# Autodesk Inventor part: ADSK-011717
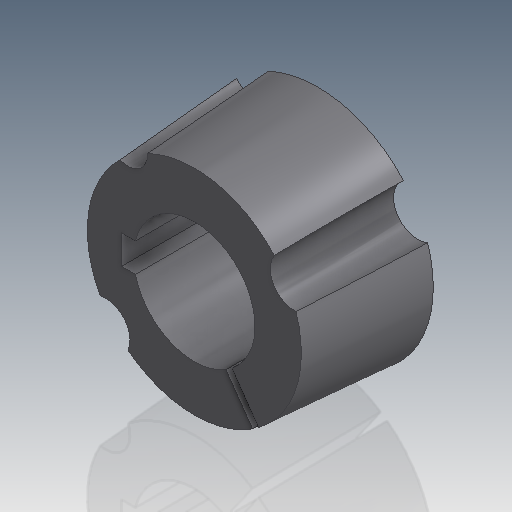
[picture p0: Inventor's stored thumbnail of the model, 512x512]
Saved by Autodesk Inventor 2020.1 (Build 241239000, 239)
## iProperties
Created: 1999-11
Part Number: ADSK-011717
Material: Acier doux
Description: BUSH,TL,1.00B,1.875
Document SubType Name: Modeling
Designer: dmcquary
Density: 7.86 g/cm^3
Appearance: Metal-Steel(Polish)
Mass: 210.363 g
Surface Area: 85.9295 cm^2
Volume: 26.7637 cm^3
Control State: 0
Checked Out: False
Last Check In By: sspink
Last Check In Date: 1999-12-22
Master: False
Shininess: 0.0
Length Units: 11269
Angle Units: 11279
Time Units: 11290
Mass Units: 11283
Length Display Precision: 3
Angle Display Precision: 2
Compacted: True
Dimensions: 47,6x47,6x25,4 mm
Mass: 0,21 kg
DocNumber: ADSK-011717.ipt
Folder: 01 - Themengebiete\Simplification\01 - Packaging machine\
VDS_Category: 3D Komponenten
Density: 0.0
Volumn: 0.0
Area: 0.0
PropertySet Name: Model Information
Author: dmcquary
Revision Number: -
Title: BUSH,TL,1.00B,1.875
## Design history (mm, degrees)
node "Solide1"
  node "Extrusion1" dims "d1" = 25.4, "d2" = -4 deg
  node "Extrusion2" dims "d8" = 25.4, "d9" = 0
  node "Hole1" dims "d15" = 10, "d16" = 9.525, "d17" = 6.35, "d18" = 60 deg, "d19" = 25.4, "d20" = 118 deg, "d36" = 6
  node "Hole2" dims "d23" = 8, "d24" = 9.525, "d25" = 6.35, "d26" = 60 deg, "d27" = 22.2, "d28" = 118 deg, "d37" = 16
  node "Extrusion3" dims "d32" = 25.4, "d33" = 0
sketch "Sketch2"
  geometry: L1 (0, 0)-(18.01, 0); L2 (9, 3)-(15, 3); L3 (15, 3)-(15, -3); L4 (15, -3)-(9, -3); L5 (9, -3)-(9, 3); C1 r 23.812 at (0, 0) reference; C2 r 12.5 at (0, 0)
  constraints: 10 end point, 2 coincident, 2 horizontal, 2 parallel, 2 perpendicular, 1 centre point
  dimensions: "d3" = 25 diameter of C2; "d4" = 6 distance of L3.end L4.end; "d6" = 3 distance from line of C1.centre L2; "d7" = 15 distance from line of L3 C2.centre
sketch "Sketch3"
  geometry: L1 (-15, 3)-(-12.135, 3) reference; L2 (0, 0)-(-23.812, 0); L3 (0, 0)-(-18.241, -15.306); L4 (0, 0)-(20.622, 11.906); C1 r 22.036 at (0, 0) reference; A1 r 23.812 centre (0, 0) between (-23.812, 0) and (-18.241, -15.306); 2 further points
  constraints: 6 end point, 3 coincident, 3 point on circle, 1 centre point, 1 parallel
  dimensions: "d10" = 47.625 diameter of A1; "d12" = 40 deg angle of L3 L2; "d14" = 170 deg angle of L4 L3
workaxis "Work Axis1"
sketch "Sketch6"
  geometry: L1 (-6.558, -7.982)-(-5.258, -8.893); L2 (-5.258, -8.893)-(-17.181, -25.921); L3 (-17.181, -25.921)-(-18.481, -25.01); L4 (-18.481, -25.01)-(-6.558, -7.982); L5 (13.658, 19.506)-(0, 0); A1 r 12.5 centre (0, 0) between (12.135, 3) and (12.135, -3) reference; A2 r 4 centre (13.658, 19.506) between (10.201, 21.517) and (16.731, 16.945) reference; A3 r 23.812 centre (0, 0) between (21.035, -11.16) and (16.731, 16.945) reference
  constraints: 10 end point, 3 parallel, 1 perpendicular
  dimensions: "d29" = 1.5875 distance of L2.end L3.end; "d30" = 0.79375 distance from line of L4 A1.centre; "d31" = 180 deg angle of L2 L5; "d34" = 10.30033 distance from line of L1 A1.centre; "d35" = 31.08768 distance from line of L3 A1.centre
node "Corps solides"
node "Corps surfaciques"
sketch "Sketch1"
  geometry: C1 r 23.812 at (0, 0)
  constraints: 1 centre point, 1 other
  dimensions: "d0" = 47.625 diameter of C1
sketch "Sketch4"
  geometry: L1 (-15, 3)-(-12.135, 3) reference; L2 (0, 0)-(-13.658, 19.506); L3 (0, 0)-(-28.935, 0); A1 r 12.5 centre (0, 0) between (-12.135, -3) and (-12.135, 3) reference; 1 further point
  constraints: 4 end point, 1 coincident, 1 parallel
  dimensions: "d21" = 23.8125 distance of L2.start L2.end; "d22" = 55 deg angle of L3 L2
